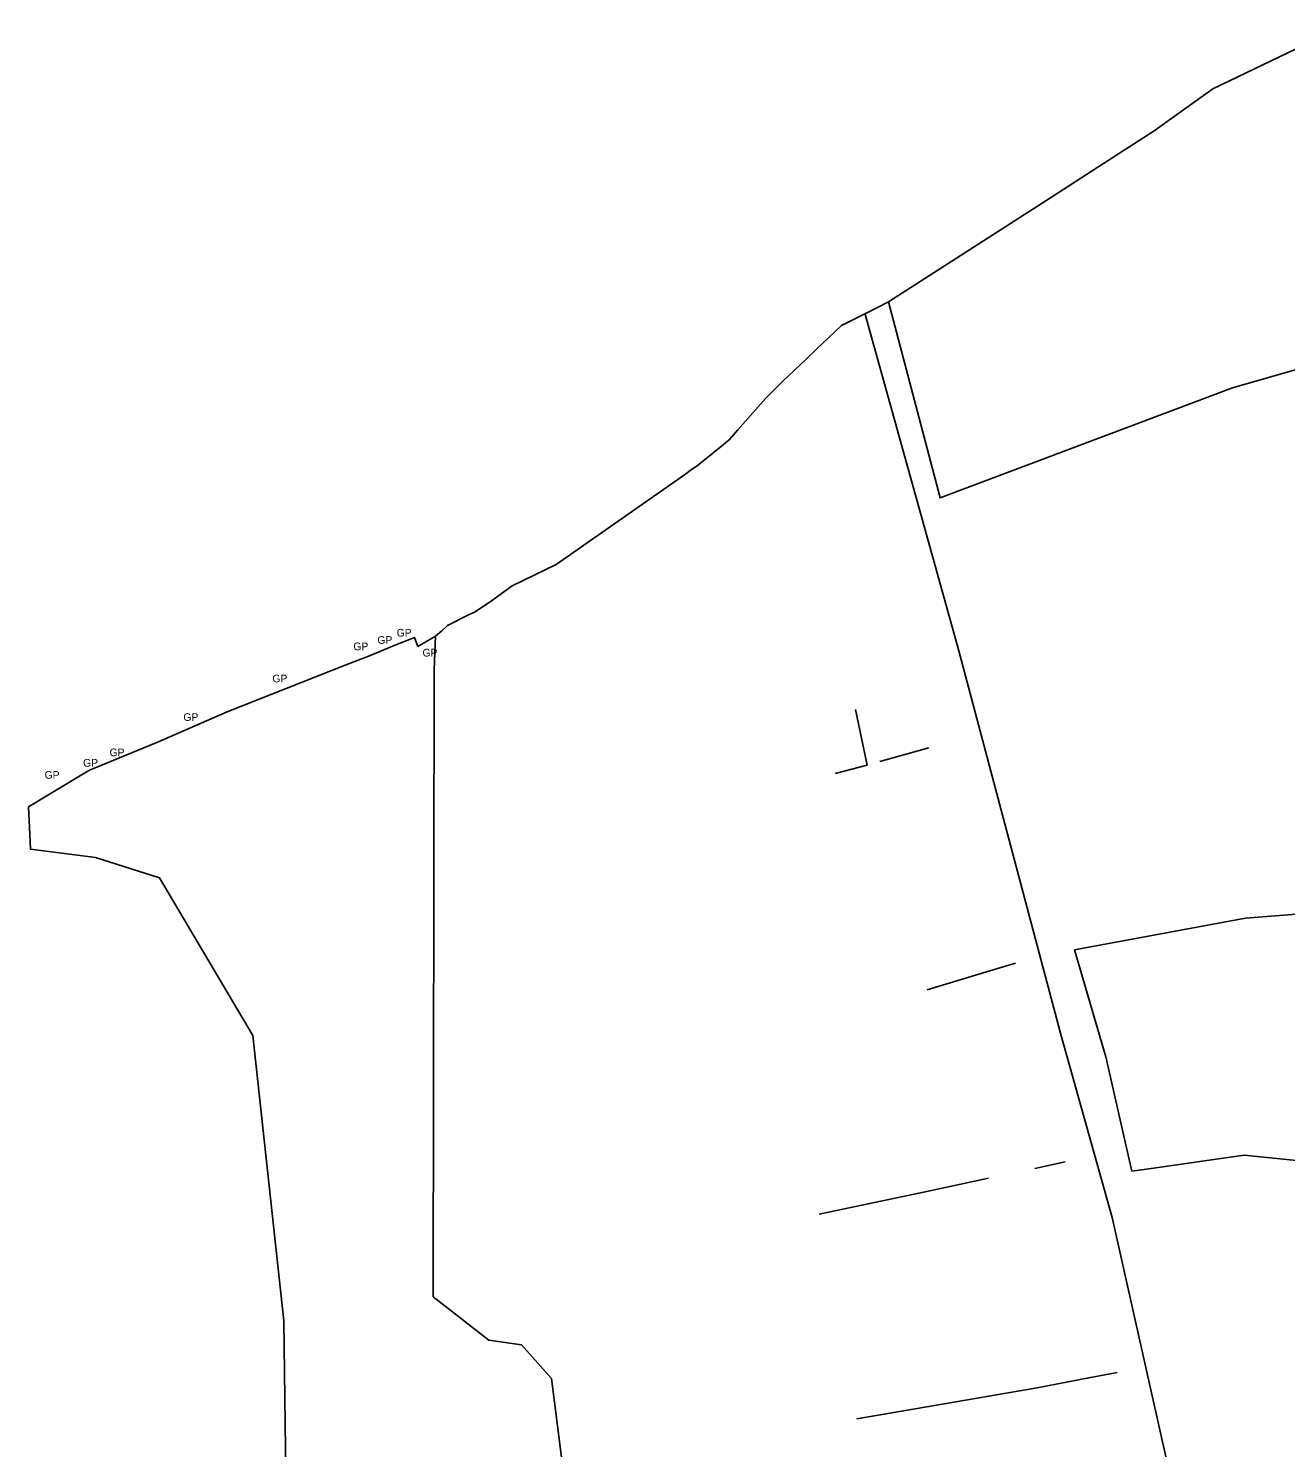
# Model space of a CAD drawing. Extents: x -615719 to -612048, y -1104937 to -1102684.
# Drawn here: x -615623.3 to -615297.1, y -1103068.2 to -1102700 of the extents above; entities that cross this region are included whole.
import ezdxf

# ---------------------------------------------------------------- set-up
doc = ezdxf.new("R2010")
doc.units = 0
for name, color, linetype in [('CESTY', 7, 'Continuous'), ('GRA_ZV', 7, 'Continuous'), ('HRA_KU_ke_zmene', 7, 'Continuous'), ('LES_ZV', 7, 'Continuous'), ('OVNE_PRE', 7, 'Continuous'), ('OVNE_SET', 7, 'Continuous'), ('POZN', 7, 'Continuous')]:
    doc.layers.add(name, color=color, linetype=linetype)

msp = doc.modelspace()

# ---------------------------------------------------------------- linework, layer by layer
at = {"layer": 'CESTY'}
msp.add_lwpolyline([(-615170.78, -1103841.28), (-615187.68, -1103757.01), (-615207.9, -1103652.82), (-615229.44, -1103551.29), (-615242.36, -1103485.26), (-615262.91, -1103378.75), (-615287.1, -1103262.29), (-615302.67, -1103181), (-615318.58, -1103113.31), (-615342.11, -1103008.46), (-615355.36, -1102961.01), (-615381.87, -1102861.47), (-615406.29, -1102773.88)], dxfattribs=at)
at = {"layer": 'GRA_ZV'}
for points in [[(-615159.43, -1102776.66), (-615186.39, -1102738.28), (-615237.78, -1102699.98), (-615251.34, -1102700.6), (-615261.92, -1102701.09), (-615294.54, -1102705.33), (-615315.96, -1102715.69), (-615331.19, -1102726.55), (-615344.34, -1102735.03), (-615359.06, -1102744.53), (-615400.09, -1102770.94), (-615386.72, -1102821.74), (-615310.85, -1102793.24), (-615282.25, -1102785.01), (-615235.47, -1102779.35), (-615196.43, -1102777.39), (-615159.43, -1102776.66)], [(-615336.95, -1102996.45), (-615343.76, -1102966.84), (-615351.82, -1102939.02), (-615307.46, -1102930.85), (-615270.06, -1102927.91), (-615242.25, -1102927.32), (-615212.49, -1102929.08), (-615079.93, -1102946.33), (-615050.17, -1102953.97), (-615031.76, -1102962), (-615016.88, -1102995.51), (-615007.68, -1103006.48), (-614983.36, -1103049.18), (-615072.78, -1103029.73), (-615073.19, -1103032.6), (-615136, -1103017.24), (-615201.48, -1103003.73), (-615223.79, -1103000.86), (-615307.86, -1102992.27), (-615333.17, -1102995.91), (-615336.95, -1102996.45)]]:
    msp.add_lwpolyline(points, dxfattribs=at)
at = {"layer": 'HRA_KU_ke_zmene'}
msp.add_lwpolyline([(-615517.62, -1102857.63), (-615518.04, -1102866.31), (-615518.25, -1103029.09), (-615503.85, -1103040.29), (-615495.31, -1103041.51), (-615487.57, -1103050.28), (-615484.43, -1103074.77), (-615486.68, -1103088.43), (-615495.74, -1103091.38), (-615499.96, -1103112.27), (-615496.1, -1103128.93), (-615488.36, -1103141.7), (-615490.04, -1103155.4), (-615486.87, -1103164.37), (-615494.6, -1103171.43), (-615493.86, -1103178.25), (-615507.51, -1103179.69), (-615510.18, -1103180.39), (-615524.58, -1103185.19), (-615552.35, -1103190.35)], dxfattribs=at)
at = {"layer": 'LES_ZV'}
for p, q in [((-615405.68, -1102891.09), (-615408.71, -1102876.73)), ((-615402.35, -1102890.16), (-615389.63, -1102886.63)), ((-615413.93, -1102893.29), (-615405.68, -1102891.09)), ((-615354.25, -1102994.05), (-615362.13, -1102995.73))]:
    msp.add_line(p, q, dxfattribs=at)
for points in [[(-615367.14, -1102942.51), (-615373.83, -1102944.52), (-615386.93, -1102948.46), (-615390.04, -1102949.4)], [(-615374.18, -1102998.29), (-615390.62, -1103001.79), (-615418.12, -1103007.64)], [(-615340.76, -1103048.69), (-615348.12, -1103050.06), (-615361.5, -1103052.65), (-615390.71, -1103057.67), (-615408.33, -1103060.7)]]:
    msp.add_lwpolyline(points, dxfattribs=at)
at = {"layer": 'OVNE_PRE'}
msp.add_line((-615622.81, -1102910.89), (-615623.29, -1102901.9), dxfattribs=at)
msp.add_lwpolyline([(-615622.81, -1102910.89), (-615622.75, -1102912.89), (-615607.83, -1102914.81), (-615605.85, -1102915.06), (-615589.24, -1102920.38), (-615565.01, -1102961.29), (-615557, -1103035.31), (-615555.71, -1103135.3), (-615554.02, -1103159.05)], dxfattribs=at)
at = {"layer": 'OVNE_SET'}
for points in [[(-615237.78, -1102699.98), (-615251.34, -1102700.6), (-615261.92, -1102701.09), (-615294.54, -1102705.33), (-615315.96, -1102715.69), (-615331.19, -1102726.55), (-615344.34, -1102735.03), (-615359.06, -1102744.53), (-615400.09, -1102770.94)], [(-615412.28, -1102777.02), (-615409.2, -1102775.48), (-615402.98, -1102772.38), (-615400.09, -1102770.94)], [(-615412.28, -1102777.02), (-615417.35, -1102781.84), (-615418.53, -1102782.97), (-615421.4, -1102785.7), (-615424.73, -1102788.87), (-615427.25, -1102791.28), (-615432.03, -1102796), (-615439.17, -1102804.14), (-615441.44, -1102806.73), (-615443.9, -1102808.72), (-615449.78, -1102813.46), (-615451.19, -1102814.45), (-615453.08, -1102815.78), (-615486.35, -1102839.11)], [(-615486.35, -1102839.11), (-615497.72, -1102844.62), (-615503.1, -1102848.49), (-615507.38, -1102851.31), (-615509.25, -1102852.25), (-615514.53, -1102854.91), (-615516.01, -1102856.32), (-615517.62, -1102857.63), (-615522.26, -1102860.38)], [(-615528.42, -1102860.07), (-615523.14, -1102858), (-615522.26, -1102860.38)], [(-615623.29, -1102901.9), (-615608.43, -1102893.06), (-615607.45, -1102892.44), (-615589.94, -1102885.23), (-615571.7, -1102877.33), (-615541.1, -1102865.15), (-615534.82, -1102862.73), (-615528.42, -1102860.07)]]:
    msp.add_lwpolyline(points, dxfattribs=at)

# ---------------------------------------------------------------- texts
at = {"layer": 'POZN'}
for p in [(-615532.72, -1102859.65), (-615527.73, -1102857.77), (-615538.96, -1102861.32), (-615521.02, -1102862.94), (-615559.98, -1102869.65), (-615583.07, -1102879.65), (-615602.22, -1102888.82), (-615609.08, -1102891.52), (-615619.07, -1102894.65)]:
    msp.add_text('GP', height=2, dxfattribs=at).set_placement(p)

doc.saveas('drawing.dxf')
